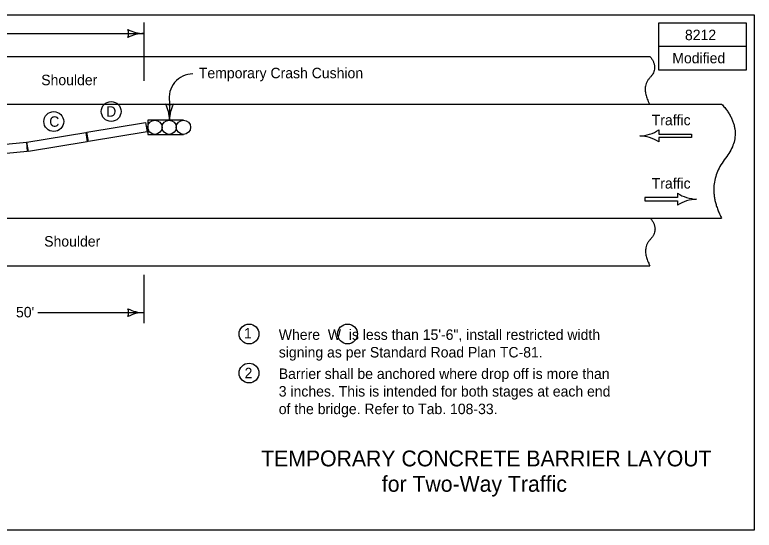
# Model space of a CAD drawing. Extents: x 8045 to 81668, y 6217 to 16762.
# Drawn here: x 15655 to 16587, y 11856 to 12506 of the extents above; entities that cross this region are included whole.
import ezdxf

# ---------------------------------------------------------------- set-up
doc = ezdxf.new("R2010")
doc.units = 0
doc.layers.add('dsnStdLineWork', color=7, linetype='Continuous')

msp = doc.modelspace()

# ---------------------------------------------------------------- linework, layer by layer
at = {"layer": 'dsnStdLineWork'}
for p, q in [((13482.42, 12505.54), (16587.42, 12505.54)), ((16587.42, 12505.54), (16587.42, 11855.54)), ((15818.05, 12495.74), (15818.05, 12422.13)), ((14933.2, 12481.93), (15818.05, 12481.93)), ((15107.61, 12452.97), (16456.03, 12452.97)), ((15850.47, 12395.58), (15850.47, 12373.08)), ((15077.61, 12392.97), (16546.38, 12392.97)), ((15868.06, 12372.71), (15823.05, 12372.71)), ((15823.05, 12372.71), (15823.05, 12354.7)), ((15824.26, 12360.41), (15822.98, 12360.12)), ((16467.12, 12360.34), (16467.12, 12355.09)), ((15822.5, 12356.72), (15822.5, 12356.72)), ((15823.05, 12354.7), (15868.06, 12354.7)), ((16443.21, 12352.84), (16443.21, 12352.84)), ((16467.12, 12355.09), (16508.37, 12355.09)), ((16508.37, 12350.59), (16467.12, 12350.59)), ((16467.12, 12350.59), (16467.12, 12345.34)), ((16508.37, 12355.09), (16508.37, 12350.59)), ((16490.74, 12275.23), (16449.49, 12275.23)), ((16449.49, 12275.23), (16449.49, 12270.73)), ((16490.74, 12280.48), (16490.74, 12275.23)), ((16449.49, 12270.73), (16490.74, 12270.73)), ((16490.74, 12270.73), (16490.74, 12265.48)), ((16514.65, 12272.98), (16514.65, 12272.98)), ((15077.61, 12248.97), (16546.38, 12248.97)), ((15107.61, 12188.97), (16456.03, 12188.97)), ((15818.05, 12177.69), (15818.05, 12116.47)), ((15684.61, 12129.91), (15818.05, 12129.91)), ((16587.42, 11855.54), (13482.42, 11855.54))]:
    msp.add_line(p, q, dxfattribs=at)
msp.add_lwpolyline([(16577.42, 12495.54), (16577.42, 12435.54), (16467.42, 12435.54), (16467.42, 12495.54), (16577.42, 12495.54), (16577.42, 12465.54), (16467.42, 12465.54)], dxfattribs=at)
for points in [[(15746.32, 12357.49), (15820.33, 12369.62), (15822.27, 12357.78), (15748.26, 12345.65)], [(15670.82, 12345.11), (15744.84, 12357.25), (15746.78, 12345.4), (15672.76, 12333.27)], [(15595.41, 12337.89), (15670.08, 12344.99), (15671.21, 12333.04), (15596.55, 12325.94)]]:
    msp.add_lwpolyline(points, close=True, dxfattribs=at)
for centre, radius in [((15776.95, 12383.61), 12.5), ((15704.59, 12370.92), 12.5), ((15832.05, 12363.71), 9), ((15832.05, 12363.71), 9), ((15850.05, 12363.71), 9), ((15850.05, 12363.71), 9), ((15868.06, 12363.71), 9), ((15868.06, 12363.71), 9), ((15950.73, 12103.01), 12.5), ((16074.89, 12103.02), 12.5), ((15950.73, 12053.75), 12.5)]:
    msp.add_circle(centre, radius, dxfattribs=at)
for centre, radius, start, end in [((15782.42, 12481.93), 16.42, 342.26665, 17.73335), ((15818.05, 12524.43), 42.5, 241.92751, 270), ((15818.05, 12439.43), 42.5, 90, 118.07249), ((15879.98, 12400.97), 30, 90, 190.35373), ((15850.47, 12408.71), 16.42, 252.26665, 287.73335), ((15807.97, 12373.08), 42.5, 0, 28.07249), ((15892.97, 12373.08), 42.5, 151.92751, 180), ((16441.22, 12401.15), 48.36, 272.35199, 302.38203), ((16441.22, 12304.52), 48.36, 57.61797, 87.64801), ((16516.64, 12321.3), 48.36, 237.61797, 267.64801), ((16516.64, 12224.66), 48.36, 92.35199, 122.38203), ((15782.42, 12129.91), 16.42, 342.26665, 17.73335), ((15818.05, 12172.41), 42.5, 241.92751, 270), ((15818.05, 12087.41), 42.5, 90, 118.07249)]:
    msp.add_arc(centre, radius, start, end, dxfattribs=at)
for points in [[(16456.03, 12452.97), (16467.82, 12438.86), (16444.22, 12413.85), (16455.56, 12393)], [(16546.38, 12392.97), (16577.83, 12358.54), (16524.45, 12290.49), (16546.38, 12248.97)], [(16456.49, 12248.94), (16468.29, 12234.82), (16444.69, 12209.81), (16456.03, 12188.97)]]:
    msp.add_open_spline(points, degree=2, dxfattribs=at)

# ---------------------------------------------------------------- texts
for s, height, p in [('8212', 13.2, (16500.14, 12473.54)), ('Modified', 13.2, (16484.19, 12444.34)), ('Temporary Crash Cushion', 13.2, (15887.49, 12425.53)), ('Shoulder', 13.2, (15688.81, 12416.75)), ('D', 13.2, (15770.63, 12377.01)), ('C', 13.2, (15698.89, 12364.32)), ('Traffic', 13.2, (16458.21, 12366.24)), ('Traffic', 13.2, (16458.21, 12286.38)), ('Shoulder', 13.2, (15692.54, 12213.28)), ("50'", 13.2, (15657, 12123.94)), ('1', 13.2, (15944.43, 12097.32)), ('Where  W  is less than 15\'-6", install restricted width', 13.2, (15988.2, 12095.59)), ('signing as per Standard Road Plan TC-81.', 13.2, (15988.2, 12073.39)), ('2', 13.2, (15945.11, 12047.15)), ('Barrier shall be anchored where drop off is more than ', 13.2, (15988.2, 12046.33)), ('3 inches. This is intended for both stages at each end ', 13.2, (15988.2, 12024.13)), ('of the bridge. Refer to Tab. 108-33.', 13.2, (15988.2, 12001.93)), ('TEMPORARY CONCRETE BARRIER LAYOUT', 20, (15965.96, 11936.03)), ('for Two-Way Traffic', 20, (16118.08, 11904.03))]:
    msp.add_text(s, height=height, dxfattribs=at).set_placement(p)

doc.saveas('drawing.dxf')
